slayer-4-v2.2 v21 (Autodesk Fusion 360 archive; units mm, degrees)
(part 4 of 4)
sketch "GEMFAN (1)" plane through (28.9566, -14, -18.6867) normal (0, 1, 0) x axis (1, 0, 0)
  line L1 (-10.4908, -14.3859) -> (-10.1901, -14.3781)
  curve K1 (-10.483, -14.4948) -> (-10.4908, -14.3859)
  curve K2 (-10.5931, -14.5653) -> (-10.483, -14.4948)
  curve K3 (-10.7079, -14.5442) -> (-10.5931, -14.5653)
  curve K4 (-10.7742, -14.4778) -> (-10.7079, -14.5442)
  curve K5 (-10.7699, -14.4076) -> (-10.7742, -14.4778)
  curve K6 (-10.6369, -14.3377) -> (-10.7699, -14.4076)
  curve K7 (-10.3998, -14.1951) -> (-10.6369, -14.3377)
  curve K8 (-10.395, -14.0009) -> (-10.3998, -14.1951)
  curve K9 (-10.5015, -13.864) -> (-10.395, -14.0009)
  curve K10 (-10.6812, -13.7716) -> (-10.5015, -13.864)
  curve K11 (-10.9429, -13.7551) -> (-10.6812, -13.7716)
  curve K12 (-11.2037, -13.8495) -> (-10.9429, -13.7551)
  curve K13 (-11.2265, -14.0791) -> (-11.2037, -13.8495)
  line L2 (-10.929, -14.0702) -> (-11.2265, -14.0791)
  curve K14 (-10.9223, -13.971) -> (-10.929, -14.0702)
  curve K15 (-10.8331, -13.9324) -> (-10.9223, -13.971)
  curve K16 (-10.7425, -13.9474) -> (-10.8331, -13.9324)
  curve K17 (-10.6916, -13.9988) -> (-10.7425, -13.9474)
  curve K18 (-10.6957, -14.0423) -> (-10.6916, -13.9988)
  curve K19 (-10.7834, -14.0869) -> (-10.6957, -14.0423)
  curve K20 (-11.0349, -14.1976) -> (-10.7834, -14.0869)
  curve K21 (-11.1148, -14.3159) -> (-11.0349, -14.1976)
  curve K22 (-11.0915, -14.4624) -> (-11.1148, -14.3159)
  curve K23 (-10.963, -14.6292) -> (-11.0915, -14.4624)
  curve K24 (-10.7625, -14.7352) -> (-10.963, -14.6292)
  curve K25 (-10.5047, -14.7548) -> (-10.7625, -14.7352)
  curve K26 (-10.1945, -14.6291) -> (-10.5047, -14.7548)
  curve K27 (-10.1901, -14.3781) -> (-10.1945, -14.6291)
  line L3 (-11.8415, -13.8508) -> (-11.5336, -13.8239)
  line L4 (-11.5206, -14.5794) -> (-11.8415, -13.8508)
  line L5 (-12.001, -14.6214) -> (-11.5206, -14.5794)
  line L6 (-11.8962, -14.8594) -> (-12.001, -14.6214)
  line L7 (-11.1079, -14.7905) -> (-11.8962, -14.8594)
  line L8 (-11.5336, -13.8239) -> (-11.1079, -14.7905)
  line L9 (-12.3694, -14.7351) -> (-12.7189, -14.7657)
  line L10 (-12.2506, -14.8904) -> (-12.3694, -14.7351)
  line L11 (-11.9363, -14.8629) -> (-12.2506, -14.8904)
  line L12 (-12.7364, -13.9291) -> (-11.9363, -14.8629)
  line L13 (-13.0722, -13.9585) -> (-12.7364, -13.9291)
  line L14 (-13.0208, -14.9578) -> (-13.0722, -13.9585)
  line L15 (-12.6985, -14.9296) -> (-13.0208, -14.9578)
  line L16 (-12.7189, -14.7657) -> (-12.6985, -14.9296)
  line L17 (-12.7902, -14.194) -> (-12.7471, -14.5511)
  line L18 (-12.5283, -14.532) -> (-12.7902, -14.194)
  line L19 (-12.7471, -14.5511) -> (-12.5283, -14.532)
  line L20 (-13.6675, -14.0106) -> (-13.3256, -13.9807)
  line L21 (-13.7246, -14.3542) -> (-13.6675, -14.0106)
  line L22 (-14.0693, -14.0457) -> (-13.7246, -14.3542)
  line L23 (-14.4094, -14.0755) -> (-14.0693, -14.0457)
  line L24 (-13.7747, -14.6033) -> (-14.4094, -14.0755)
  line L25 (-13.5964, -15.0082) -> (-13.7747, -14.6033)
  line L26 (-13.2879, -14.9812) -> (-13.5964, -15.0082)
  line L27 (-13.4662, -14.5764) -> (-13.2879, -14.9812)
  line L28 (-13.3256, -13.9807) -> (-13.4662, -14.5764)
  line L29 (-15.3329, -14.1563) -> (-14.508, -14.0841)
  line L30 (-15.242, -14.3627) -> (-15.3329, -14.1563)
  line L31 (-14.7256, -14.3175) -> (-15.242, -14.3627)
  line L32 (-14.6579, -14.4711) -> (-14.7256, -14.3175)
  line L33 (-15.137, -14.513) -> (-14.6579, -14.4711)
  line L34 (-15.0502, -14.7101) -> (-15.137, -14.513)
  line L35 (-14.5711, -14.6682) -> (-15.0502, -14.7101)
  line L36 (-14.4872, -14.8588) -> (-14.5711, -14.6682)
  line L37 (-15.0186, -14.9053) -> (-14.4872, -14.8588)
  line L38 (-14.9221, -15.1242) -> (-15.0186, -14.9053)
  line L39 (-14.0822, -15.0507) -> (-14.9221, -15.1242)
  line L40 (-14.508, -14.0841) -> (-14.0822, -15.0507)
  line L41 (-15.5177, -14.1725) -> (-15.092, -15.139)
  line L42 (-16.0308, -14.2173) -> (-15.5177, -14.1725)
  curve K28 (-16.2385, -14.2602) -> (-16.0308, -14.2173)
  curve K29 (-16.3213, -14.3588) -> (-16.2385, -14.2602)
  curve K30 (-16.2986, -14.5195) -> (-16.3213, -14.3588)
  curve K31 (-16.2021, -14.6551) -> (-16.2986, -14.5195)
  curve K32 (-16.0632, -14.7413) -> (-16.2021, -14.6551)
  curve K33 (-15.9382, -14.77) -> (-16.0632, -14.7413)
  curve K34 (-16.0027, -14.8127) -> (-15.9382, -14.77)
  curve K35 (-16.0295, -14.8678) -> (-16.0027, -14.8127)
  curve K36 (-16.0462, -14.9316) -> (-16.0295, -14.8678)
  line L43 (-16.0719, -15.2248) -> (-16.0462, -14.9316)
  line L44 (-15.7241, -15.1943) -> (-16.0719, -15.2248)
  line L45 (-15.6896, -14.8846) -> (-15.7241, -15.1943)
  curve K37 (-15.6667, -14.8052) -> (-15.6896, -14.8846)
  curve K38 (-15.6012, -14.7762) -> (-15.6667, -14.8052)
  line L46 (-15.574, -14.7738) -> (-15.6012, -14.7762)
  line L47 (-15.4012, -15.1661) -> (-15.574, -14.7738)
  line L48 (-15.092, -15.139) -> (-15.4012, -15.1661)
  line L49 (-15.7842, -14.6025) -> (-15.6544, -14.5911)
  curve K39 (-15.8716, -14.5964) -> (-15.7842, -14.6025)
  curve K40 (-15.9349, -14.5705) -> (-15.8716, -14.5964)
  curve K41 (-15.9789, -14.5161) -> (-15.9349, -14.5705)
  curve K42 (-15.98, -14.4416) -> (-15.9789, -14.5161)
  curve K43 (-15.8762, -14.4065) -> (-15.98, -14.4416)
  line L50 (-15.741, -14.3947) -> (-15.8762, -14.4065)
  line L51 (-15.6544, -14.5911) -> (-15.741, -14.3947)
  line L52 (-17.3586, -14.3335) -> (-16.5975, -14.2669)
  line L53 (-17.2671, -14.5412) -> (-17.3586, -14.3335)
  line L54 (-16.8152, -14.5017) -> (-17.2671, -14.5412)
  line L55 (-16.7409, -14.6704) -> (-16.8152, -14.5017)
  line L56 (-17.1269, -14.7042) -> (-16.7409, -14.6704)
  line L57 (-17.0409, -14.8994) -> (-17.1269, -14.7042)
  line L58 (-16.6549, -14.8656) -> (-17.0409, -14.8994)
  line L59 (-16.481, -15.2605) -> (-16.6549, -14.8656)
  line L60 (-16.1718, -15.2335) -> (-16.481, -15.2605)
  line L61 (-16.5975, -14.2669) -> (-16.1718, -15.2335)
  line L62 (-17.3008, -15.1666) -> (-17.6503, -15.1971)
  line L63 (-17.182, -15.3219) -> (-17.3008, -15.1666)
  line L64 (-16.8677, -15.2944) -> (-17.182, -15.3219)
  line L65 (-17.6678, -14.3606) -> (-16.8677, -15.2944)
  line L66 (-18.0036, -14.3899) -> (-17.6678, -14.3606)
  line L67 (-17.9522, -15.3893) -> (-18.0036, -14.3899)
  line L68 (-17.6298, -15.3611) -> (-17.9522, -15.3893)
  line L69 (-17.6503, -15.1971) -> (-17.6298, -15.3611)
  line L70 (-17.7215, -14.6255) -> (-17.6785, -14.9825)
  line L71 (-17.4597, -14.9634) -> (-17.7215, -14.6255)
  line L72 (-17.6785, -14.9825) -> (-17.4597, -14.9634)
  line L73 (-18.7652, -14.4566) -> (-18.4778, -14.4314)
  line L74 (-18.9048, -15.0241) -> (-18.7652, -14.4566)
  line L75 (-19.1403, -14.4894) -> (-18.9048, -15.0241)
  line L76 (-19.4305, -14.5148) -> (-19.1403, -14.4894)
  line L77 (-19.0048, -15.4813) -> (-19.4305, -14.5148)
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sketch "4040R" plane through (28.9566, -14, -18.6867) normal (0, 1, 0) x axis (1, 0, 0)
  line L1 (-33.0077, -32.8191) -> (-33.3332, -32.6673)
  line L2 (-33.2827, -33.4089) -> (-33.0077, -32.8191)
  line L3 (-33.1297, -33.4803) -> (-33.2827, -33.4089)
  line L4 (-31.9595, -33.2707) -> (-33.1297, -33.4803)
  line L5 (-31.8959, -33.1344) -> (-31.9595, -33.2707)
  line L6 (-32.7768, -32.7236) -> (-31.8959, -33.1344)
  line L7 (-32.6912, -32.5399) -> (-32.7768, -32.7236)
  line L8 (-32.8442, -32.4686) -> (-32.6912, -32.5399)
  line L9 (-32.9299, -32.6522) -> (-32.8442, -32.4686)
  line L10 (-33.2553, -32.5004) -> (-32.9299, -32.6522)
  line L11 (-33.3332, -32.6673) -> (-33.2553, -32.5004)
  line L12 (-32.2417, -33.1763) -> (-32.8547, -32.8905)
  line L13 (-33.0532, -33.3161) -> (-32.2417, -33.1763)
  line L14 (-32.8547, -32.8905) -> (-33.0532, -33.3161)
  curve K1 (-32.0085, -32.5902) -> (-32.4197, -32.4588)
  curve K2 (-31.713, -32.5485) -> (-32.0085, -32.5902)
  curve K3 (-31.5184, -32.3394) -> (-31.713, -32.5485)
  curve K4 (-31.473, -32.127) -> (-31.5184, -32.3394)
  curve K5 (-31.5365, -31.9314) -> (-31.473, -32.127)
  curve K6 (-31.6993, -31.7527) -> (-31.5365, -31.9314)
  curve K7 (-32.0063, -31.5723) -> (-31.6993, -31.7527)
  curve K8 (-32.4155, -31.4414) -> (-32.0063, -31.5723)
  curve K9 (-32.7112, -31.4824) -> (-32.4155, -31.4414)
  curve K10 (-32.9067, -31.6921) -> (-32.7112, -31.4824)
  curve K11 (-32.9097, -32.0666) -> (-32.9067, -31.6921)
  curve K12 (-32.4197, -32.4588) -> (-32.9097, -32.0666)
  curve K13 (-32.7487, -32.0011) -> (-32.3397, -32.2873)
  curve K14 (-32.7694, -31.7561) -> (-32.7487, -32.0011)
  curve K15 (-32.568, -31.6147) -> (-32.7694, -31.7561)
  curve K16 (-32.0863, -31.7439) -> (-32.568, -31.6147)
  curve K17 (-31.6768, -32.0302) -> (-32.0863, -31.7439)
  curve K18 (-31.6575, -32.2769) -> (-31.6768, -32.0302)
  curve K19 (-31.8405, -32.4151) -> (-31.6575, -32.2769)
  curve K20 (-32.3397, -32.2873) -> (-31.8405, -32.4151)
  line L15 (-32.0226, -30.7067) -> (-32.3481, -30.5549)
  line L16 (-32.2977, -31.2965) -> (-32.0226, -30.7067)
  line L17 (-32.1446, -31.3678) -> (-32.2977, -31.2965)
  line L18 (-30.9744, -31.1582) -> (-32.1446, -31.3678)
  line L19 (-30.9108, -31.0219) -> (-30.9744, -31.1582)
  line L20 (-31.7918, -30.6111) -> (-30.9108, -31.0219)
  line L21 (-31.7062, -30.4275) -> (-31.7918, -30.6111)
  line L22 (-31.8592, -30.3561) -> (-31.7062, -30.4275)
  line L23 (-31.9448, -30.5398) -> (-31.8592, -30.3561)
  line L24 (-32.2703, -30.388) -> (-31.9448, -30.5398)
  line L25 (-32.3481, -30.5549) -> (-32.2703, -30.388)
  line L26 (-31.2567, -31.0639) -> (-31.8696, -30.778)
  line L27 (-32.0681, -31.2037) -> (-31.2567, -31.0639)
  line L28 (-31.8696, -30.778) -> (-32.0681, -31.2037)
  curve K21 (-31.0234, -30.4777) -> (-31.4347, -30.3464)
  curve K22 (-30.7279, -30.436) -> (-31.0234, -30.4777)
  curve K23 (-30.5334, -30.227) -> (-30.7279, -30.436)
  curve K24 (-30.4879, -30.0145) -> (-30.5334, -30.227)
  curve K25 (-30.5514, -29.8189) -> (-30.4879, -30.0145)
  curve K26 (-30.7142, -29.6403) -> (-30.5514, -29.8189)
  curve K27 (-31.0213, -29.4599) -> (-30.7142, -29.6403)
  curve K28 (-31.4304, -29.3289) -> (-31.0213, -29.4599)
  curve K29 (-31.7261, -29.3699) -> (-31.4304, -29.3289)
  curve K30 (-31.9216, -29.5797) -> (-31.7261, -29.3699)
  curve K31 (-31.9246, -29.9542) -> (-31.9216, -29.5797)
  curve K32 (-31.4347, -30.3464) -> (-31.9246, -29.9542)
  curve K33 (-31.7637, -29.8887) -> (-31.3547, -30.1748)
  curve K34 (-31.7844, -29.6437) -> (-31.7637, -29.8887)
  curve K35 (-31.5829, -29.5022) -> (-31.7844, -29.6437)
  curve K36 (-31.1013, -29.6314) -> (-31.5829, -29.5022)
  curve K37 (-30.6918, -29.9178) -> (-31.1013, -29.6314)
  curve K38 (-30.6724, -30.1644) -> (-30.6918, -29.9178)
  curve K39 (-30.8554, -30.3026) -> (-30.6724, -30.1644)
  curve K40 (-31.3547, -30.1748) -> (-30.8554, -30.3026)
  line L29 (-30.2203, -29.541) -> (-31.5797, -28.907)
  line L30 (-29.9392, -28.9382) -> (-30.2203, -29.541)
  curve K41 (-29.847, -28.6448) -> (-29.9392, -28.9382)
  curve K42 (-29.9058, -28.4333) -> (-29.847, -28.6448)
  curve K43 (-30.0844, -28.2812) -> (-29.9058, -28.4333)
  curve K44 (-30.372, -28.2611) -> (-30.0844, -28.2812)
  curve K45 (-30.633, -28.4916) -> (-30.372, -28.2611)
  curve K46 (-30.6501, -28.3516) -> (-30.633, -28.4916)
  curve K47 (-30.7613, -28.1179) -> (-30.6501, -28.3516)
  line L31 (-31.021, -27.7089) -> (-30.7613, -28.1179)
  line L32 (-31.1265, -27.9352) -> (-31.021, -27.7089)
  line L33 (-30.9276, -28.247) -> (-31.1265, -27.9352)
  curve K48 (-30.8008, -28.4642) -> (-30.9276, -28.247)
  curve K49 (-30.7525, -28.5979) -> (-30.8008, -28.4642)
  curve K50 (-30.7546, -28.6968) -> (-30.7525, -28.5979)
  curve K51 (-30.7948, -28.8) -> (-30.7546, -28.6968)
  line L34 (-30.8921, -29.0086) -> (-30.7948, -28.8)
  line L35 (-31.4958, -28.7271) -> (-30.8921, -29.0086)
  line L36 (-31.5797, -28.907) -> (-31.4958, -28.7271)
  line L37 (-30.556, -28.6946) -> (-30.7364, -29.0813)
  curve K52 (-30.4406, -28.5136) -> (-30.556, -28.6946)
  curve K53 (-30.3097, -28.4459) -> (-30.4406, -28.5136)
  curve K54 (-30.1709, -28.4666) -> (-30.3097, -28.4459)
  curve K55 (-30.045, -28.6106) -> (-30.1709, -28.4666)
  curve K56 (-30.086, -28.8607) -> (-30.045, -28.6106)
  line L38 (-30.2866, -29.291) -> (-30.086, -28.8607)
  line L39 (-30.7364, -29.0813) -> (-30.2866, -29.291)
extrude "Extrude10" sketch "GEMFAN (1)" blind -0.1 (= "-d44")
extrude "Extrude8" sketch "4040R" blind -0.1 (= "-d44")
component_from_bodies "Body->Comp1"
component_from_bodies "Body->Comp2"
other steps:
base_feature "Base Feature1" bodies "CW Prop"
base_feature "Base Feature1" bodies "CCW Prop"
create_component "CreateComponent1"
create_component "CreateComponent2"
remove_body "RemoveBody2"
remove_body "RemoveBody3"
named bodies: "CW Prop", "CCW Prop"

design "runcam_phoenix_2"
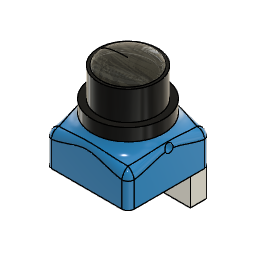
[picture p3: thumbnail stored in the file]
sketch "Skizze1" plane through (0, 0, 0) normal (0, 0, 1) x axis (1, 0, 0)
  line L1 (20, 0) -> (0, 0)
  line L2 (20, 20) -> (20, 0)
  line L3 (0, 20) -> (20, 20)
  line L4 (0, 0) -> (0, 20)
  point P1 (0, 0)
  point P2 (0, 0)
  point P3 (20, 0)
  point P5 (0, 20)
  horizontal L1
  vertical L2
  horizontal L3
  vertical L4
  coincident P1 P2
  dimension "d1" distance P2 P3 = 20
  dimension "d2" distance P2 P5 = 20
extrude "Extrusion1" new body sketch "Skizze1" along normal blind 8
sketch "Skizze2" plane through (0, 0, 8) normal (0, 0, 1) x axis (-1, 0, 0)
  line L1 (0, 0) -> (0, -20)
  line L2 (-20, 0) -> (0, 0)
  line L3 (-20, -20) -> (-20, 0)
  line L4 (0, -20) -> (-20, -20)
  circle C1 centre (-10, -10) radius 8.15
  dimension "d5" diameter C1 = 16.3
extrude "Extrusion2" add sketch "Skizze2" profile of C1 along normal blind 13
fillet "Abrundung1" radius 1.5
fillet "Abrundung2" radius 5
fillet "Abrundung3" radius 2
sphere_primitive "Grundkörper Kugel" Diameter 13
scale "Maßstab" ScaleZ 0.2475
split "Teilen1"
work_plane "Arbeitsebene" AlongDistance -13
split "Teilen2"
sketch "Skizze4" plane through (20, 0, 0) normal (1, 0, 0) x axis (0, 1, 0)
  curve K1 (18.5, 6.1577) -> (1.5, 6.1577)
  line L1 (1.5, 0) -> (1.5, 6.1577)
  line L2 (18.5, 0) -> (1.5, 0)
  line L3 (18.5, 6.1577) -> (18.5, 0)
  circle C1 centre (10, 8.5) radius 0.975
  point P6 (10, 8.5)
  dimension "d19" diameter C1 = 1.95
  dimension "d20" distance L2 P6 = 8.5
extrude "Extrusion3" cut sketch "Skizze4" profile of C1 against normal blind 4
sketch "Skizze5" plane through (0, 0, 0) normal (-1, 0, 0) x axis (0, -1, 0)
  curve K1 (-1.5, 6.1577) -> (-18.5, 6.1577)
  line L1 (-18.5, 0) -> (-18.5, 6.1577)
  line L2 (-1.5, 0) -> (-18.5, 0)
  line L3 (-1.5, 6.1577) -> (-1.5, 0)
  curve K2 (-10.9281, 8.2013) -> (-9.0719, 8.2013)
  arc A1 centre (-10, 8.5) radius 0.975 clockwise from (-9.0719, 8.2013) to (-10.9281, 8.2013)
extrude "Extrusion4" cut sketch "Skizze5" profile of A1 against normal blind 4
sketch "Skizze7" plane through (0, 0, 0) normal (0, 0, -1) x axis (1, 0, 0)
  line L1 (20, -1.5) -> (20, -18.5)
  line L2 (1.5, 0) -> (18.5, 0)
  line L3 (18.5, -20) -> (1.5, -20)
  line L4 (9.5607, -19.5607) -> (19.5607, -19.5607)
  line L5 (9.5607, -15.5607) -> (9.5607, -19.5607)
  line L6 (19.5607, -15.5607) -> (9.5607, -15.5607)
  line L7 (19.5607, -19.5607) -> (19.5607, -15.5607)
  line L8 (0, -18.5) -> (0, -1.5)
  arc A1 centre (18.5, -18.5) radius 1.5 clockwise from (20, -18.5) to (18.5, -20)
  arc A2 centre (18.5, -1.5) radius 1.5 clockwise from (18.5, 0) to (20, -1.5)
  arc A3 centre (1.5, -1.5) radius 1.5 clockwise from (0, -1.5) to (1.5, 0)
  arc A4 centre (1.5, -18.5) radius 1.5 clockwise from (1.5, -20) to (0, -18.5)
  point P14 (19.5607, -19.5607)
  point P15 (9.5607, -19.5607)
  point P17 (19.5607, -15.5607)
  horizontal L4
  vertical L5
  horizontal L6
  vertical L7
  midpoint A1 P14
  dimension "d25" distance P14 P15 = 10
  dimension "d26" distance P14 P17 = 4
extrude "Extrusion5" new body sketch "Skizze7" profile of L4 L5 L6 L7 along normal blind 7
work_plane "WorkPlane2" AlongDistance -6
split_face "SplitFace1"
offset_faces "OffsetFaces1" distance 1
extrude "Extrude6" add of existing geometry blind 2
extrude "Extrude7" cut of existing geometry blind -1
offset_faces "OffsetFaces2" distance -1
offset_faces "OffsetFaces3" distance -0.5

design "M2 x 0.4mm Thread 5mm LONG SOCKET HEAD CAP SCREW"
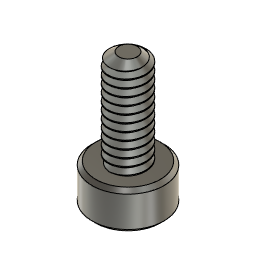
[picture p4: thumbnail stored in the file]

design "M3 x 0.5mm Thread 6mm LONG SOCKET HEAD CAP SCREW"
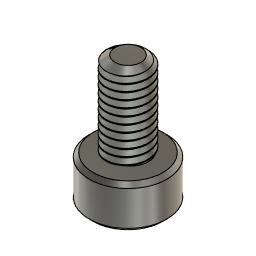
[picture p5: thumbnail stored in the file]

design "CADDXFPV Ratel 2.1mm"
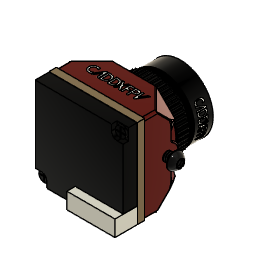
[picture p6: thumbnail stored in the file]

design "EACHINE CCW TYRO79-1607-2800KV"
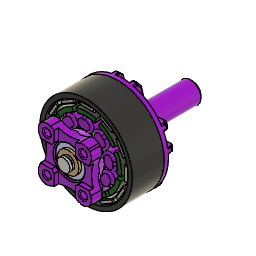
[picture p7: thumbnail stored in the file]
